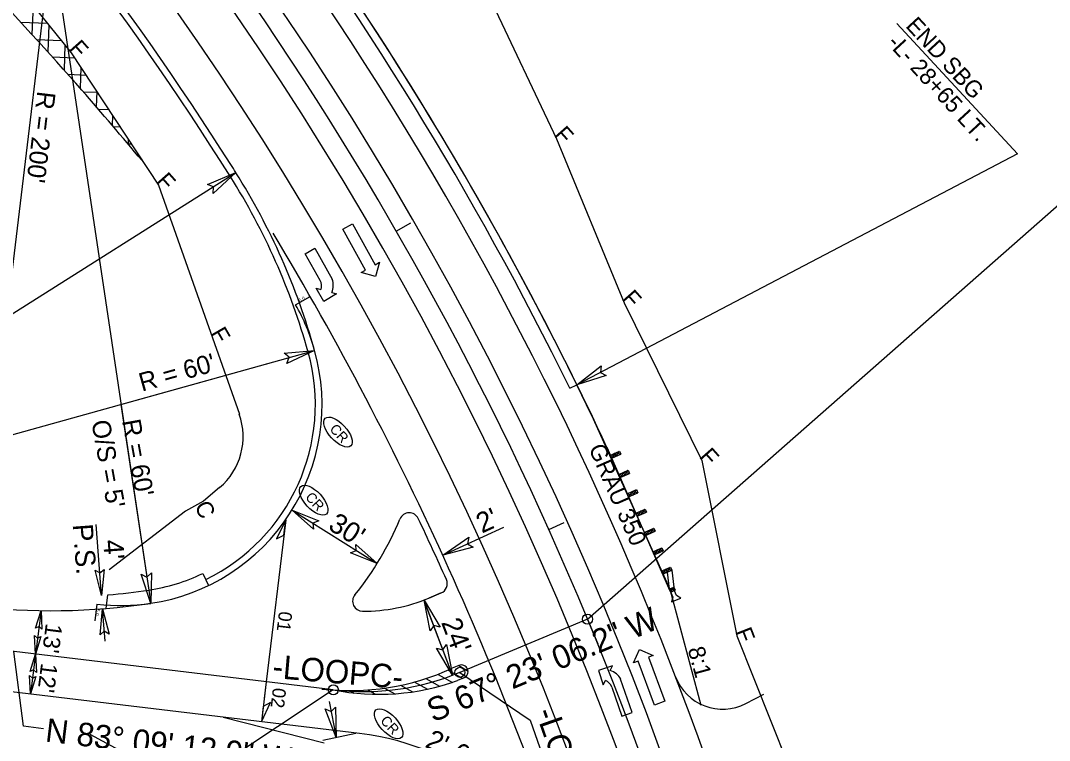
# Model space of a CAD drawing. Extents: x 1702862 to 1704514, y 793768 to 796215.
# Drawn here: x 1703743.4 to 1704050.5, y 794472 to 794686.7 of the extents above; entities that cross this region are included whole.
import ezdxf

# ---------------------------------------------------------------- set-up
doc = ezdxf.new("R2010")
doc.units = 0
for name, color, linetype in [('Default', 7, 'Continuous'), ('Prop Conc 2ft 6in Curb and Gutter', 7, 'Continuous'), ('Prop Conc 5in Monolithic Surface Mount Island', 7, 'Continuous'), ('Prop Conc Shoulder Berm Gutter', 7, 'Continuous'), ('Prop Dimension', 7, 'Continuous'), ('Prop Dimension Text', 7, 'Continuous'), ('Prop DSN Text', 7, 'Continuous'), ('Prop EOT', 7, 'Continuous'), ('Prop Guardrail', 7, 'Continuous'), ('Prop Guardrail Anchor Unit CELL', 7, 'Continuous'), ('Prop Horizontal Alignment', 7, 'Continuous'), ('Prop Horizontal Alignment Direction Label', 7, 'Continuous'), ('Prop Horizontal Alignment Station Label', 7, 'Continuous'), ('Prop Horizontal Alignment Tick Large', 7, 'Continuous'), ('Prop Horizontal Alignment Tick Small', 7, 'Continuous'), ('Prop Lane Arrow CELL', 7, 'Continuous'), ('Prop Lane Lines', 7, 'Continuous'), ('Prop Leader Line Medium', 7, 'Continuous'), ('Prop Paint Stripe', 7, 'Continuous'), ('Prop Paved Shoulder', 7, 'Continuous'), ('Prop Rem of Exist Asph Pvmt', 7, 'Continuous'), ('Prop SS Cut Line', 7, 'Continuous'), ('Prop SS Fill Line', 7, 'Continuous'), ('Prop SS Misc', 7, 'Continuous'), ('Prop SS Transition Line', 7, 'Continuous'), ('Prop Structure Anchor Unit CELL', 7, 'Continuous'), ('Prop Superelevation  Arrow CELL', 7, 'Continuous'), ('Prop Superelevation Label', 7, 'Continuous'), ('Prop Terminator CELL', 7, 'Continuous'), ('Prop WCR CELL', 7, 'Continuous')]:
    doc.layers.add(name, color=color, linetype=linetype)

msp = doc.modelspace()

# ---------------------------------------------------------------- linework, layer by layer
at = {"layer": 'Prop Conc 2ft 6in Curb and Gutter'}
for centre, radius, start, end in [((1702985.28, 794122.36), 970.46, 32.25438, 42.65517), ((1703638.54, 794534.6), 198, 15.5759, 32.2542), ((1703773.4, 794572.2), 58, 295.8355, 15.5759)]:
    msp.add_arc(centre, radius, start, end, dxfattribs=at)
at = {"layer": 'Prop Conc 5in Monolithic Surface Mount Island'}
for p, q in [((1703865.32, 794514.43), (1703868.95, 794515.94)), ((1703868.95, 794515.94), (1703865.32, 794514.43))]:
    msp.add_line(p, q, dxfattribs=at)
for centre, radius, start, end in [((1703859.42, 794536.86), 3, 25.344, 157.6692), ((1703859.42, 794536.86), 3, 25.344, 157.6692), ((1703773.4, 794572.2), 90, 320.8717, 337.6692), ((1703773.4, 794572.2), 90, 320.8717, 337.6692), ((1702989.11, 794124.65), 966, 24.15464, 25.34397), ((1702989.11, 794124.65), 966, 24.15464, 25.34397), ((1703867.79, 794518.71), 3, 292.6149, 24.1546), ((1703867.79, 794518.71), 3, 292.6149, 24.1546), ((1703845.54, 794513.51), 3, 140.8717, 269.797), ((1703845.54, 794513.51), 3, 140.8717, 269.797), ((1703845.71, 794561.51), 51, 269.797, 292.6149), ((1703845.71, 794561.51), 51, 269.797, 292.6149)]:
    msp.add_arc(centre, radius, start, end, dxfattribs=at)
at = {"layer": 'Prop Conc Shoulder Berm Gutter'}
msp.add_arc((1702988.97, 794124.56), 1026.16, 26.22656, 37.0429, dxfattribs=at)
at = {"layer": 'Prop Dimension'}
for p, q in [((1703752.73, 794710.66), (1703728.81, 794512.1)), ((1703752.73, 794710.66), (1703782.26, 794512.85)), ((1703638.54, 794534.6), (1703807.68, 794641.34)), ((1703825.51, 794601.94), (1703829.85, 794604.42)), ((1703638.54, 794534.6), (1703831.2, 794588.31)), ((1703773.4, 794572.2), (1703831.2, 794588.31)), ((1703773.4, 794572.2), (1703782.26, 794512.85)), ((1703824.44, 794540.66), (1703849.88, 794524.75)), ((1703767.61, 794515.23), (1703766, 794536.37)), ((1703869.41, 794527.25), (1703887.64, 794535.59)), ((1703766.23, 794512.63), (1703765.63, 794507.66)), ((1703872.37, 794491.4), (1703863.84, 794513.84)), ((1703768.65, 794501.53), (1703767.91, 794511.23)), ((1703872.37, 794491.4), (1703864.61, 794511.8)), ((1703835.58, 794483.54), (1703837.58, 794472.8)), ((1703843.46, 794474.05), (1703833.63, 794471.98))]:
    msp.add_line(p, q, dxfattribs=at)
for start, end in [(15.5759, 29.7174), (263.1332, 278.4921)]:
    msp.add_arc((1703773.4, 794572.2), 60, start, end, dxfattribs=at)
at = {"layer": 'Prop DSN Text'}
for p, q in [((1703749.54, 794510.69), (1703747.87, 794497.72)), ((1703747.87, 794497.72), (1703746.34, 794485.81))]:
    msp.add_line(p, q, dxfattribs=at)
at = {"layer": 'Prop EOT'}
for p, q in [((1703844.62, 794474.01), (1703740.76, 794486.48)), ((1703959.85, 794482.97), (1703965.31, 794485.8))]:
    msp.add_line(p, q, dxfattribs=at)
for centre, radius, start, end in [((1702989.11, 794124.65), 1018, 14.75888, 42.70907), ((1702989.11, 794124.65), 968, 32.4282, 42.70916), ((1702985.36, 794121.76), 972.72, 32.28652, 32.45319), ((1703638.54, 794534.6), 200, 15.5759, 32.2542), ((1703773.4, 794572.2), 60, 278.4921, 15.5759), ((1703752.73, 794710.66), 200, 263.1332, 278.4921), ((1703952.94, 794496.29), 15, 201.086, 297.4155), ((1703835.09, 794394.58), 80, 17.697, 83.1536)]:
    msp.add_arc(centre, radius, start, end, dxfattribs=at)
at = {"layer": 'Prop Guardrail'}
msp.add_arc((1702988.97, 794124.56), 1026.16, 25.07101, 37.18325, dxfattribs=at)
at = {"layer": 'Prop Guardrail Anchor Unit CELL'}
for p, q in [((1703918.44, 794559.41), (1703937.21, 794516.59)), ((1703919.46, 794557.08), (1703922.21, 794558.29)), ((1703921.24, 794556.77), (1703922.21, 794558.29)), ((1703922.21, 794558.29), (1703922.61, 794557.37)), ((1703919.46, 794557.08), (1703919.86, 794556.17)), ((1703921.24, 794556.77), (1703919.46, 794557.08)), ((1703920.83, 794557.69), (1703919.86, 794556.17)), ((1703919.86, 794556.17), (1703922.61, 794557.37)), ((1703919.86, 794556.17), (1703921.24, 794556.77)), ((1703920.83, 794557.69), (1703921.24, 794556.77)), ((1703922.61, 794557.37), (1703920.83, 794557.69)), ((1703921.99, 794551.31), (1703924.79, 794552.54)), ((1703923.79, 794551.01), (1703924.79, 794552.54)), ((1703924.79, 794552.54), (1703925.19, 794551.62)), ((1703921.99, 794551.31), (1703923.79, 794551.01)), ((1703923.39, 794551.93), (1703922.39, 794550.4)), ((1703922.39, 794550.4), (1703925.19, 794551.62)), ((1703923.39, 794551.93), (1703923.79, 794551.01)), ((1703925.19, 794551.62), (1703923.39, 794551.93)), ((1703924.52, 794545.54), (1703927.31, 794546.77)), ((1703925.92, 794546.15), (1703924.92, 794544.63)), ((1703925.92, 794546.15), (1703926.32, 794545.24)), ((1703927.71, 794545.85), (1703925.92, 794546.15)), ((1703926.32, 794545.24), (1703927.31, 794546.77)), ((1703927.31, 794546.77), (1703927.71, 794545.85)), ((1703924.52, 794545.54), (1703926.32, 794545.24)), ((1703924.92, 794544.63), (1703927.71, 794545.85)), ((1703927.05, 794539.77), (1703929.83, 794540.99)), ((1703928.44, 794540.38), (1703927.45, 794538.85)), ((1703927.45, 794538.85), (1703930.23, 794540.07)), ((1703928.44, 794540.38), (1703928.84, 794539.46)), ((1703930.23, 794540.07), (1703928.44, 794540.38)), ((1703928.84, 794539.46), (1703929.83, 794540.99)), ((1703929.83, 794540.99), (1703930.23, 794540.07)), ((1703927.05, 794539.77), (1703927.45, 794538.85)), ((1703927.05, 794539.77), (1703928.84, 794539.46)), ((1703929.58, 794534), (1703932.45, 794535.26)), ((1703929.58, 794534), (1703931.42, 794533.71)), ((1703931.01, 794534.63), (1703929.98, 794533.08)), ((1703929.98, 794533.08), (1703932.85, 794534.34)), ((1703931.01, 794534.63), (1703931.42, 794533.71)), ((1703932.85, 794534.34), (1703931.01, 794534.63)), ((1703931.42, 794533.71), (1703932.45, 794535.26)), ((1703932.45, 794535.26), (1703932.85, 794534.34)), ((1703932.11, 794528.23), (1703934.85, 794529.43)), ((1703932.11, 794528.23), (1703933.88, 794527.91)), ((1703933.48, 794528.83), (1703932.51, 794527.31)), ((1703932.51, 794527.31), (1703935.26, 794528.52)), ((1703933.48, 794528.83), (1703933.88, 794527.91)), ((1703935.26, 794528.52), (1703933.48, 794528.83)), ((1703933.88, 794527.91), (1703934.85, 794529.43)), ((1703934.85, 794529.43), (1703935.26, 794528.52)), ((1703934.64, 794522.46), (1703937.44, 794523.69)), ((1703934.64, 794522.46), (1703936.44, 794522.15)), ((1703936.04, 794523.07), (1703935.04, 794521.54)), ((1703935.04, 794521.54), (1703937.84, 794522.77)), ((1703936.04, 794523.07), (1703936.44, 794522.15)), ((1703937.84, 794522.77), (1703936.04, 794523.07)), ((1703936.44, 794522.15), (1703937.44, 794523.69)), ((1703936.44, 794522.15), (1703937, 794517.05)), ((1703937.44, 794523.69), (1703937.84, 794522.77)), ((1703937.84, 794522.77), (1703938.38, 794517.65)), ((1703937, 794517.05), (1703938.38, 794517.65)), ((1703938.78, 794516.74), (1703937, 794517.05)), ((1703937.85, 794516.83), (1703937.29, 794516.59)), ((1703937.29, 794516.59), (1703938.08, 794514.7)), ((1703937.41, 794516.14), (1703938.38, 794517.65)), ((1703937.41, 794516.14), (1703938.78, 794516.74)), ((1703938.42, 794517.07), (1703937.85, 794516.83)), ((1703938.38, 794517.65), (1703938.58, 794517.2)), ((1703938.38, 794517.65), (1703938.78, 794516.74)), ((1703939.2, 794515.18), (1703938.42, 794517.07)), ((1703938.08, 794514.7), (1703937.73, 794513.29)), ((1703937.73, 794513.29), (1703940.45, 794514.42)), ((1703940.45, 794514.42), (1703939.2, 794515.18))]:
    msp.add_line(p, q, dxfattribs=at)
at = {"layer": 'Prop Horizontal Alignment'}
for p, q in [((1703912.65, 794508.14), (1703874.55, 794492.27)), ((1703836.77, 794487.04), (1703719.97, 794501.07))]:
    msp.add_line(p, q, dxfattribs=at)
for centre, radius, start, end in [((1702989.11, 794124.65), 1000, 351.25916, 42.70907), ((1703845.71, 794561.51), 75, 263.1536, 292.6149)]:
    msp.add_arc(centre, radius, start, end, dxfattribs=at)
at = {"layer": 'Prop Horizontal Alignment Direction Label'}
for p, q in [((1703744.31, 794476.19), (1703741.41, 794498.49)), ((1703750.3, 794475.45), (1703744.31, 794476.19))]:
    msp.add_line(p, q, dxfattribs=at)
at = {"layer": 'Prop Horizontal Alignment Station Label'}
for p, q in [((1703912.65, 794508.14), (1704114.85, 794686.06)), ((1703874.55, 794492.27), (1703895.55, 794478.02)), ((1703836.77, 794487.04), (1703744.62, 794426.04))]:
    msp.add_line(p, q, dxfattribs=at)
msp.add_lwpolyline([(1703895.55, 794478.02), (1703931.64, 794374.68)], dxfattribs=at)
for centre in [(1703912.65, 794508.14), (1703874.55, 794492.27), (1703836.77, 794487.04)]:
    msp.add_circle(centre, 1.5, dxfattribs=at)
at = {"layer": 'Prop Horizontal Alignment Tick Large'}
msp.add_line((1703912.65, 794508.14), (1703915.73, 794500.76), dxfattribs=at)
at = {"layer": 'Prop Horizontal Alignment Tick Small'}
for p, q in [((1703855.57, 794623.89), (1703859.9, 794626.39)), ((1703901.08, 794534.89), (1703905.64, 794536.95)), ((1703816.75, 794489.45), (1703816.16, 794484.48))]:
    msp.add_line(p, q, dxfattribs=at)
at = {"layer": 'Prop Lane Arrow CELL'}
for p, q in [((1703839.59, 794624.51), (1703842.48, 794626.11)), ((1703842.48, 794626.11), (1703849.27, 794613.87)), ((1703846.38, 794612.27), (1703839.59, 794624.51)), ((1703828.35, 794617.15), (1703831.23, 794618.77)), ((1703832.85, 794609.18), (1703828.35, 794617.15)), ((1703831.23, 794618.77), (1703836.41, 794609.58)), ((1703849.27, 794613.87), (1703850.58, 794614.59)), ((1703850.58, 794614.59), (1703849.39, 794610.33)), ((1703845.07, 794611.54), (1703846.38, 794612.27)), ((1703849.39, 794610.33), (1703845.07, 794611.54)), ((1703833.9, 794602.94), (1703831.65, 794606.83)), ((1703831.65, 794606.83), (1703833.08, 794606.44)), ((1703837.71, 794605.15), (1703833.9, 794602.94)), ((1703836.28, 794605.54), (1703837.71, 794605.15)), ((1703926.33, 794495.09), (1703928.11, 794499.13)), ((1703928.11, 794499.13), (1703932.22, 794497.32)), ((1703932.22, 794497.32), (1703930.82, 794496.79)), ((1703920.08, 794494.17), (1703915.9, 794492.78)), ((1703919.43, 794492.83), (1703920.08, 794494.17)), ((1703927.73, 794495.62), (1703926.33, 794495.09)), ((1703932.68, 794482.52), (1703927.73, 794495.62)), ((1703930.82, 794496.79), (1703935.76, 794483.69)), ((1703915.9, 794492.78), (1703917.32, 794488.51)), ((1703917.32, 794488.51), (1703917.97, 794489.85)), ((1703919.87, 794487.86), (1703922.84, 794479.2)), ((1703925.96, 794480.27), (1703922.53, 794490.25)), ((1703935.76, 794483.69), (1703932.68, 794482.52)), ((1703922.84, 794479.2), (1703925.96, 794480.27))]:
    msp.add_line(p, q, dxfattribs=at)
for centre, radius, start, end in [((1703830.02, 794607.57), 3.28, 339.7935, 29.4516), ((1703831.52, 794607.73), 5.25, 335.4639, 20.7756), ((1703917.9, 794487.82), 5.25, 27.6389, 72.9506), ((1703916.78, 794486.81), 3.28, 18.9628, 68.621)]:
    msp.add_arc(centre, radius, start, end, dxfattribs=at)
at = {"layer": 'Prop Lane Lines'}
for radius, start, end in [(1006, 0.00687, 42.70907), (994, 359.40932, 42.70907), (980, 359.40932, 42.70907), (968, 17.6382, 31.00789)]:
    msp.add_arc((1702989.11, 794124.65), radius, start, end, dxfattribs=at)
at = {"layer": 'Prop Leader Line Medium'}
for q in [(1704004.97, 794685.82), (1703909.49, 794578.04)]:
    msp.add_line((1704040.99, 794646.92), q, dxfattribs=at)
at = {"layer": 'Prop Paint Stripe'}
for p, q in [((1703874.23, 794494.3), (1703872.25, 794493.48)), ((1703874.22, 794494.3), (1703876.98, 794492.64)), ((1703868.04, 794491.64), (1703872.33, 794489.28)), ((1703871.02, 794492.91), (1703875.45, 794490.48)), ((1703856.86, 794488.42), (1703860.44, 794486.45)), ((1703860.95, 794489.4), (1703864.87, 794487.25)), ((1703864.36, 794490.41), (1703868.51, 794488.13)), ((1703875.77, 794490.61), (1703873.79, 794489.79)), ((1703841.67, 794486.83), (1703843, 794486.1)), ((1703846.99, 794487.02), (1703849.37, 794485.72)), ((1703852.02, 794487.56), (1703855.1, 794485.87))]:
    msp.add_line(p, q, dxfattribs=at)
for centre, radius, start, end in [((1703875, 794492.46), 2, 22.6149, 112.6149), ((1703841.63, 794560.61), 73.78, 263.5676, 294.5181), ((1703875, 794492.46), 2, 292.6149, 22.6149), ((1703850.32, 794555.26), 69.55, 258.7681, 289.7186)]:
    msp.add_arc(centre, radius, start, end, dxfattribs=at)
at = {"layer": 'Prop Paved Shoulder'}
for p, q in [((1703907.4, 794577.02), (1703909.49, 794578.04)), ((1703913.87, 794569.03), (1703909.49, 794578.04)), ((1703913.88, 794569.04), (1703937.26, 794517.08)), ((1703797.8, 794521.79), (1703799.55, 794518.19)), ((1703769.02, 794511.33), (1703769.51, 794515.38)), ((1703937.26, 794517.08), (1703946.43, 794482.44)), ((1703803.86, 794478.91), (1703834.03, 794471.26))]:
    msp.add_line(p, q, dxfattribs=at)
for centre, radius, start, end in [((1702988.97, 794124.56), 1023.83, 26.22656, 37.0429), ((1703773.4, 794572.2), 56, 278.4921, 295.8355), ((1703752.73, 794710.66), 196, 274.9119, 278.4921)]:
    msp.add_arc(centre, radius, start, end, dxfattribs=at)
at = {"layer": 'Prop Rem of Exist Asph Pvmt'}
for p, q in [((1703747.15, 794691.23), (1703746.8, 794682.65)), ((1703743.47, 794686.26), (1703751.41, 794685.94)), ((1703751.91, 794685.31), (1703751.6, 794677.4)), ((1703748.26, 794681.06), (1703755.57, 794680.77)), ((1703756.68, 794679.38), (1703756.39, 794672.06)), ((1703752.98, 794675.87), (1703759.5, 794675.61)), ((1703761.42, 794672.69), (1703761.17, 794666.58)), ((1703757.61, 794670.68), (1703762.88, 794670.47)), ((1703762.1, 794665.49), (1703766.27, 794665.33)), ((1703766.14, 794665.53), (1703765.95, 794661)), ((1703766.54, 794660.31), (1703769.65, 794660.19)), ((1703770.85, 794658.36), (1703770.73, 794655.41)), ((1703770.97, 794655.13), (1703773.04, 794655.05)), ((1703775.57, 794651.2), (1703775.52, 794649.83)), ((1703775.41, 794649.95), (1703776.42, 794649.91))]:
    msp.add_line(p, q, dxfattribs=at)
msp.add_spline([(1703779.68, 794644.96), (1703761.75, 794665.91), (1703731.32, 794699.4), (1703700.82, 794732.47), (1703669.4, 794765.36)], degree=3, dxfattribs=at)
at = {"layer": 'Prop SS Cut Line'}
for p, q in [((1703802.82, 794547.39), (1703798.04, 794543.32)), ((1703798.04, 794543.32), (1703792.65, 794540.32))]:
    msp.add_line(p, q, dxfattribs=at)
at = {"layer": 'Prop SS Fill Line'}
for p, q in [((1703728.84, 794713.99), (1703758.51, 794677.1)), ((1703880.62, 794699.51), (1703903.35, 794651.42)), ((1703758.51, 794677.1), (1703784.55, 794637.56)), ((1703903.35, 794651.42), (1703923.62, 794602.55)), ((1703784.55, 794637.56), (1703808.72, 794569.3)), ((1703923.62, 794602.55), (1703946.73, 794555.43)), ((1703946.73, 794555.43), (1703957.17, 794503.16))]:
    msp.add_line(p, q, dxfattribs=at)
at = {"layer": 'Prop SS Transition Line'}
for p, q in [((1703792.65, 794540.32), (1703769.82, 794522.9)), ((1703957.17, 794503.16), (1703976.48, 794454.84)), ((1703783.41, 794463.43), (1703764.24, 794473.69))]:
    msp.add_line(p, q, dxfattribs=at)
msp.add_arc((1703789.86, 794562.62), 20, 310.3906, 19.4922, dxfattribs=at)
at = {"layer": 'Prop Superelevation  Arrow CELL'}
for p, q in [((1703822.56, 794537.79), (1703816.75, 794489.45)), ((1703816.75, 794489.45), (1703815.32, 794477.53))]:
    msp.add_line(p, q, dxfattribs=at)
for points in [[(1703822.56, 794537.79), (1703819.86, 794532.07), (1703822.01, 794533.2)], [(1703815.32, 794477.53), (1703818.02, 794483.25), (1703815.87, 794482.12)]]:
    msp.add_lwpolyline(points, close=True, dxfattribs=at)
at = {"layer": 'Prop Terminator CELL'}
for points in [[(1703799.25, 794637.83), (1703807.68, 794641.34), (1703800.89, 794635.14), (1703801.01, 794637.11)], [(1703822.1, 794587.49), (1703831.2, 794588.31), (1703822.86, 794584.43), (1703823.56, 794586.28)], [(1703918.18, 794580.87), (1703909.49, 794578.04), (1703916.76, 794583.68), (1703916.48, 794581.72)], [(1703830.81, 794534.97), (1703824.44, 794540.66), (1703832.41, 794537.44), (1703830.7, 794536.74)], [(1703878.49, 794529.65), (1703869.41, 794527.25), (1703877.19, 794532.62), (1703876.8, 794530.63)], [(1703843.51, 794530.44), (1703849.88, 794524.75), (1703841.91, 794527.97), (1703843.61, 794528.66)], [(1703768.34, 794522.95), (1703767.61, 794515.23), (1703765.67, 794522.79), (1703767.1, 794521.92)], [(1703782.54, 794521.98), (1703782.26, 794512.85), (1703779.42, 794521.59), (1703781.16, 794520.68)], [(1703865.64, 794504.62), (1703863.84, 794513.84), (1703868.68, 794505.72), (1703866.73, 794506.24)], [(1703747.93, 794505.45), (1703749.54, 794510.69), (1703749.8, 794505.18), (1703748.94, 794505.98)], [(1703767.18, 794503.5), (1703767.91, 794511.23), (1703769.85, 794503.66), (1703768.42, 794504.54)], [(1703749.49, 794502.95), (1703747.87, 794497.72), (1703747.62, 794503.22), (1703748.48, 794502.42)], [(1703870.57, 794500.62), (1703872.37, 794491.4), (1703867.52, 794499.52), (1703869.48, 794499)], [(1703746.26, 794492.48), (1703747.87, 794497.72), (1703748.13, 794492.21), (1703747.27, 794493.01)], [(1703747.96, 794491.05), (1703746.34, 794485.81), (1703746.08, 794491.32), (1703746.95, 794490.51)], [(1703837.45, 794481.93), (1703837.58, 794472.8), (1703834.35, 794481.41), (1703836.13, 794480.57)]]:
    msp.add_lwpolyline(points, close=True, dxfattribs=at)
at = {"layer": 'Prop WCR CELL'}
for centre in [(1703838.15, 794563.95), (1703830.91, 794543.62), (1703853.29, 794476.93)]:
    msp.add_ellipse(centre, major_axis=(3.8, -4.12), ratio=0.462467, dxfattribs=at)

# ---------------------------------------------------------------- texts
at = {"layer": 'Default'}
for s, p in [('END SBG', (1704007.35, 794684.94)), ('-L- 28+65 LT.', (1704001.84, 794679.86))]:
    msp.add_text(s, height=5, rotation=312.7091, dxfattribs=at).set_placement(p)
at = {"layer": 'Prop Dimension Text'}
for s, height, rotation, p in [("R = 200'", 5.5, 263.1332, (1703748.46, 794665.83)), ('5.0', 1, 29.7174, (1703826.76, 794602.65)), ("R = 60'", 5.5, 15.5759, (1703779.63, 794575.99)), ("O/S = 5'", 5.5, 280.3746, (1703764.54, 794567.06)), ("R = 60'", 5.5, 280.3746, (1703773.7, 794567.3)), ("30'", 6, 327.9676, (1703834.89, 794535.16)), ('P.S.', 6, 274.3541, (1703758.97, 794536.36)), ("4'", 6, 274.3541, (1703768.05, 794531.66)), ('5.0', 1, 263.1332, (1703766.05, 794511.2)), ("13'", 5, 262.672, (1703750.99, 794507.02)), ("24'", 6, 290.8182, (1703868.89, 794507.17)), ('8:1', 5, 285.2906, (1703942.51, 794499.22)), ("12'", 5, 262.672, (1703749.59, 794495.21)), ('2\'-6"  ', 6, 333.7051, (1703863.86, 794470.13))]:
    msp.add_text(s, height=height, rotation=rotation, dxfattribs=at).set_placement(p)
at = {"layer": 'Prop DSN Text'}
msp.add_text("2'", height=6, rotation=24.5769, dxfattribs=at).set_placement((1703881.14, 794533.65))
at = {"layer": 'Prop Horizontal Alignment Direction Label'}
for s, rotation, p in [('S 67%%d 23\' 06.2" W', 22.6149, (1703866.55, 794477.27)), ('-LOOPC-', 355.1313, (1703818.43, 794490.61)), ('N 83%%d 09\' 12.9" W', 353.1536, (1703750.58, 794471.66))]:
    msp.add_text(s, height=7, rotation=rotation, dxfattribs=at).set_placement(p)
at = {"layer": 'Prop Horizontal Alignment Station Label'}
msp.add_text('-LOOPC- PC 10+41.27', height=7, rotation=289.3057, dxfattribs=at).set_placement((1703897.04, 794480.4))
at = {"layer": 'Prop SS Misc'}
for s, rotation, p in [('F', 311.4091, (1703757.58, 794678.17)), ('F', 311.4091, (1703902.41, 794652.48)), ('F', 311.4091, (1703783.61, 794638.63)), ('F', 311.4091, (1703922.68, 794603.62)), ('F', 299.95, (1703799.89, 794593.45)), ('F', 311.4091, (1703945.79, 794556.49)), ('C', 296.9289, (1703795.2, 794541.88)), ('F', 291.3556, (1703956.65, 794504.48))]:
    msp.add_text(s, height=5, rotation=rotation, dxfattribs=at).set_placement(p)
at = {"layer": 'Prop Structure Anchor Unit CELL'}
msp.add_text('GRAU 350', height=5, rotation=293.6862, dxfattribs=at).set_placement((1703912.88, 794559.13))
at = {"layer": 'Prop Superelevation Label'}
for s, p in [('01', (1703820.58, 794510.62)), ('02', (1703818.76, 794487.81))]:
    msp.add_text(s, height=4, rotation=263.1536, dxfattribs=at).set_placement(p)
at = {"layer": 'Prop WCR CELL'}
for p in [(1703835.47, 794564.68), (1703828.22, 794544.35), (1703850.61, 794477.66)]:
    msp.add_text('CR', height=3, rotation=312.7091, dxfattribs=at).set_placement(p)

doc.saveas('drawing.dxf')
